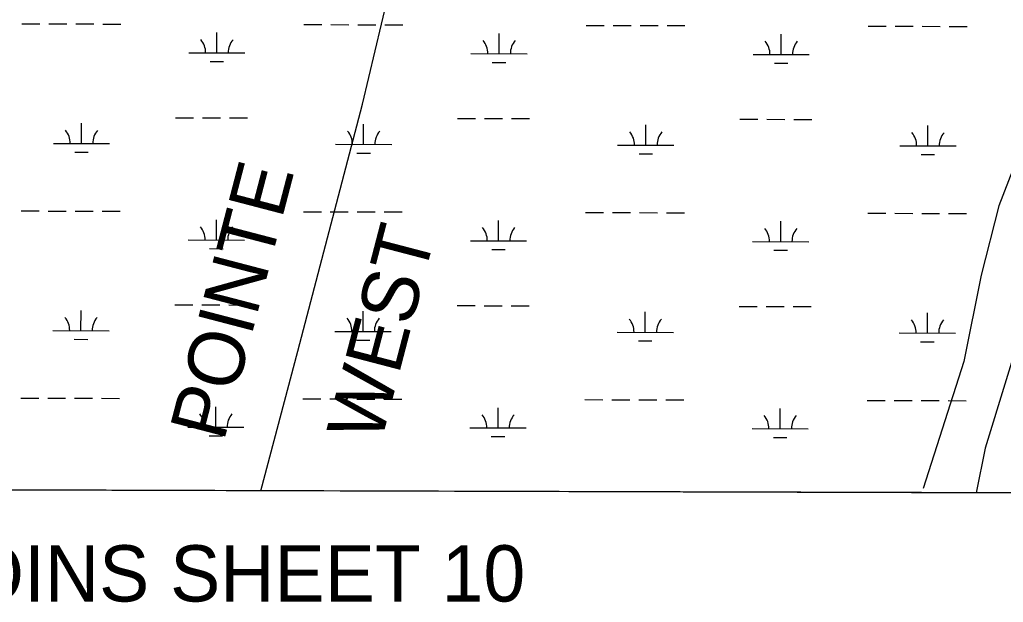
# Model space of a CAD drawing. Extents: x 3161615 to 3199515, y 867541 to 892976.
# Drawn here: x 3178180 to 3179930, y 872774 to 873810 of the extents above; entities that cross this region are included whole.
import ezdxf

# ---------------------------------------------------------------- set-up
doc = ezdxf.new("R2010")
doc.units = 0
for name, color, linetype in [('V-ANNO-TEXT', 7, 'Continuous'), ('V-GRID-FRAM', 7, 'Continuous'), ('V-SITE-VEGE', 7, 'Continuous'), ('V-TOPO-BNDY', 7, 'Continuous'), ('V-TOPO-GNAM-IDEN', 7, 'Continuous'), ('V-TOPO-SHOR', 7, 'Continuous'), ('V-WETL-SWMP', 7, 'Continuous')]:
    doc.layers.add(name, color=color, linetype=linetype)

msp = doc.modelspace()

# ---------------------------------------------------------------- linework, layer by layer
at = {"layer": 'V-GRID-FRAM'}
msp.add_lwpolyline([(3165877.4, 891195.5), (3197229, 891108.8), (3197186.7, 872920.9), (3165819.2, 873007.6), (3165877.4, 891195.5)], dxfattribs=at)
at = {"layer": 'V-SITE-VEGE'}
msp.add_line((3176872, 872977), (3180065.3, 872968.2), dxfattribs=at)
at = {"layer": 'V-TOPO-BNDY'}
for p, q in [((3178790.2, 873659.1), (3178870.4, 873998.9)), ((3178675.1, 873220.3), (3178790.2, 873659.1)), ((3178609, 872972.2), (3178675.1, 873220.3))]:
    msp.add_line(p, q, dxfattribs=at)
at = {"layer": 'V-TOPO-SHOR'}
msp.add_lwpolyline([(3180468.1, 874349.1), (3180252, 874103.5), (3180118, 873888.4), (3180025.3, 873734.7), (3179973.6, 873611.8), (3179922, 873478.5), (3179890.8, 873355.5), (3179859.6, 873201.7), (3179787.2, 872976.1)], dxfattribs=at)
at = {"layer": 'V-WETL-SWMP'}
for p, q in [((3178183.9, 873802.2), (3178215.9, 873802.1)), ((3178231.9, 873802.1), (3178263.9, 873802)), ((3178279.9, 873802), (3178311.9, 873801.9)), ((3178327.9, 873801.8), (3178359.9, 873801.7)), ((3178685.8, 873800.8), (3178717.8, 873800.8)), ((3178733.8, 873800.7), (3178765.8, 873800.6)), ((3178781.8, 873800.6), (3178813.8, 873800.5)), ((3178829.8, 873800.4), (3178861.8, 873800.4)), ((3179187.7, 873799.5), (3179219.7, 873799.4)), ((3179235.7, 873799.3), (3179267.7, 873799.2)), ((3179283.7, 873799.2), (3179315.7, 873799.1)), ((3179331.7, 873799.1), (3179363.7, 873799)), ((3179689.6, 873798.1), (3179721.6, 873798)), ((3178531, 873750.5), (3178531.1, 873786.5)), ((3179032.9, 873749.1), (3179033, 873785.1)), ((3179534.8, 873747.8), (3179534.9, 873783.8)), ((3179737.6, 873797.9), (3179769.6, 873797.8)), ((3179785.6, 873797.8), (3179817.6, 873797.7)), ((3179833.6, 873797.7), (3179865.6, 873797.6)), ((3178481, 873750.7), (3178581, 873750.4)), ((3178982.9, 873749.3), (3179082.9, 873749)), ((3179484.8, 873747.9), (3179584.8, 873747.6)), ((3178519, 873735.1), (3178543, 873735.1)), ((3179020.9, 873733.7), (3179044.9, 873733.7)), ((3179522.8, 873732.4), (3179546.8, 873732.3)), ((3180107.9, 873735), (3179897.8, 873048)), ((3178290.1, 873589.3), (3178290.2, 873625.3)), ((3178457.3, 873635.3), (3178489.3, 873635.2)), ((3178505.3, 873635.2), (3178537.3, 873635.1)), ((3178553.3, 873635), (3178585.3, 873634.9)), ((3178792, 873587.9), (3178792.1, 873623.9)), ((3178959.2, 873633.9), (3178991.2, 873633.8)), ((3179007.2, 873633.8), (3179039.2, 873633.7)), ((3179055.2, 873633.6), (3179087.2, 873633.6)), ((3179461.1, 873632.5), (3179493.1, 873632.4)), ((3179509.1, 873632.4), (3179541.1, 873632.3)), ((3179557.1, 873632.3), (3179589.1, 873632.2)), ((3179293.9, 873586.6), (3179294, 873622.6)), ((3179795.8, 873585.2), (3179795.9, 873621.2)), ((3178240.1, 873589.5), (3178340.1, 873589.2)), ((3178742, 873588.1), (3178842, 873587.8)), ((3178278.1, 873573.9), (3178302.1, 873573.9)), ((3178780, 873572.5), (3178804, 873572.5)), ((3179243.9, 873586.7), (3179343.9, 873586.4)), ((3179281.9, 873571.2), (3179305.9, 873571.1)), ((3179745.8, 873585.3), (3179845.8, 873585)), ((3179783.8, 873569.8), (3179807.8, 873569.7)), ((3178182.9, 873469.6), (3178214.9, 873469.5)), ((3178230.9, 873469.4), (3178262.9, 873469.3)), ((3178278.9, 873469.3), (3178310.9, 873469.2)), ((3178326.9, 873469.2), (3178358.9, 873469.1)), ((3178684.8, 873468.2), (3178716.8, 873468.1)), ((3178732.8, 873468), (3178764.8, 873467.9)), ((3178780.8, 873467.9), (3178812.8, 873467.8)), ((3178828.8, 873467.8), (3178860.8, 873467.7)), ((3179186.7, 873466.8), (3179218.7, 873466.7)), ((3179234.7, 873466.6), (3179266.7, 873466.6)), ((3179282.7, 873466.5), (3179314.7, 873466.4)), ((3179330.7, 873466.4), (3179362.7, 873466.3)), ((3178530.1, 873417.9), (3178530.2, 873453.9)), ((3179032, 873416.5), (3179032.1, 873452.5)), ((3179533.9, 873415.1), (3179534, 873451.1)), ((3179688.7, 873465.4), (3179720.7, 873465.3)), ((3179736.7, 873465.3), (3179768.7, 873465.2)), ((3179784.7, 873465.1), (3179816.7, 873465)), ((3179832.7, 873465), (3179864.7, 873464.9)), ((3178480.1, 873418), (3178580.1, 873417.7)), ((3178982, 873416.6), (3179082, 873416.3)), ((3179483.9, 873415.2), (3179583.9, 873414.9)), ((3178518.1, 873402.5), (3178542.1, 873402.4)), ((3179020, 873401.1), (3179044, 873401)), ((3179521.9, 873399.7), (3179545.9, 873399.6)), ((3178289.2, 873256.7), (3178289.3, 873292.7)), ((3178456.4, 873302.6), (3178488.4, 873302.5)), ((3178504.4, 873302.5), (3178536.4, 873302.4)), ((3178552.4, 873302.4), (3178584.4, 873302.3)), ((3178791.1, 873255.3), (3178791.2, 873291.3)), ((3178958.3, 873301.2), (3178990.3, 873301.2)), ((3179006.3, 873301.1), (3179038.3, 873301)), ((3179054.3, 873301), (3179086.3, 873300.9)), ((3179460.2, 873299.9), (3179492.2, 873299.8)), ((3179508.2, 873299.7), (3179540.2, 873299.6)), ((3179556.2, 873299.6), (3179588.2, 873299.5)), ((3179293, 873253.9), (3179293.1, 873289.9)), ((3179794.9, 873252.5), (3179795, 873288.5)), ((3178239.2, 873256.8), (3178339.2, 873256.5)), ((3178277.2, 873241.3), (3178301.2, 873241.2)), ((3178741.1, 873255.4), (3178841.1, 873255.1)), ((3178779.1, 873239.9), (3178803.1, 873239.8)), ((3179243, 873254), (3179343, 873253.7)), ((3179281, 873238.5), (3179305, 873238.4)), ((3179744.9, 873252.6), (3179844.9, 873252.4)), ((3179782.9, 873237.1), (3179806.9, 873237)), ((3178182, 873136.9), (3178214, 873136.8)), ((3178230, 873136.7), (3178262, 873136.7)), ((3178278, 873136.6), (3178310, 873136.5)), ((3178326, 873136.5), (3178358, 873136.4)), ((3178683.9, 873135.5), (3178715.9, 873135.4)), ((3178731.9, 873135.4), (3178763.9, 873135.3)), ((3178779.9, 873135.2), (3178811.9, 873135.1)), ((3178827.9, 873135.1), (3178859.9, 873135)), ((3179185.8, 873134.1), (3179217.8, 873134)), ((3179233.8, 873134), (3179265.8, 873133.9)), ((3179281.8, 873133.8), (3179313.8, 873133.8)), ((3179329.8, 873133.7), (3179361.8, 873133.6)), ((3178529.2, 873085.2), (3178529.3, 873121.2)), ((3179031.1, 873083.8), (3179031.2, 873119.8)), ((3179533, 873082.4), (3179533.1, 873118.4)), ((3179687.7, 873132.7), (3179719.7, 873132.6)), ((3179735.7, 873132.6), (3179767.7, 873132.5)), ((3179783.7, 873132.5), (3179815.7, 873132.4)), ((3179831.7, 873132.3), (3179863.7, 873132.2)), ((3178479.2, 873085.3), (3178579.2, 873085)), ((3178981.1, 873083.9), (3179081.1, 873083.7)), ((3179483, 873082.5), (3179583, 873082.3)), ((3178517.1, 873069.8), (3178541.1, 873069.7)), ((3179019.1, 873068.4), (3179043.1, 873068.3)), ((3179521, 873067), (3179545, 873066.9)), ((3179897.8, 873048), (3179881.4, 872968.7)), ((3179881.4, 872968.7), (3176862.9, 872977))]:
    msp.add_line(p, q, dxfattribs=at)
for centre, start, end in [((3178475.8, 873751.2), 359.0699, 40.6135), ((3178586.3, 873750.9), 139.0699, 180.6135), ((3178977.7, 873749.8), 359.0699, 40.6135), ((3179088.2, 873749.5), 139.0699, 180.6135), ((3179479.6, 873748.4), 359.0699, 40.6135), ((3179590.1, 873748.1), 139.0699, 180.6135), ((3178234.9, 873590), 359.0699, 40.6135), ((3178345.4, 873589.7), 139.0699, 180.6135), ((3178736.8, 873588.6), 359.0699, 40.6135), ((3178847.3, 873588.3), 139.0699, 180.6135), ((3179238.7, 873587.2), 359.0699, 40.6135), ((3179349.2, 873586.9), 139.0699, 180.6135), ((3179740.6, 873585.8), 359.0699, 40.6135), ((3179851.1, 873585.5), 139.0699, 180.6135), ((3178474.9, 873418.5), 359.0699, 40.6135), ((3178585.4, 873418.2), 139.0699, 180.6135), ((3178976.8, 873417.1), 359.0699, 40.6135), ((3179087.3, 873416.8), 139.0699, 180.6135), ((3179478.7, 873415.7), 359.0699, 40.6135), ((3179589.2, 873415.4), 139.0699, 180.6135), ((3178234, 873257.3), 359.0699, 40.6135), ((3178344.4, 873257), 139.0699, 180.6135), ((3178735.9, 873255.9), 359.0699, 40.6135), ((3178846.3, 873255.6), 139.0699, 180.6135), ((3179237.8, 873254.5), 359.0699, 40.6135), ((3179348.2, 873254.2), 139.0699, 180.6135), ((3179739.7, 873253.1), 359.0699, 40.6135), ((3179850.2, 873252.8), 139.0699, 180.6135), ((3178474, 873085.8), 359.0699, 40.6135), ((3178584.4, 873085.5), 139.0699, 180.6135), ((3178975.9, 873084.4), 359.0699, 40.6135), ((3179086.3, 873084.1), 139.0699, 180.6135), ((3179477.8, 873083), 359.0699, 40.6135), ((3179588.2, 873082.7), 139.0699, 180.6135)]:
    msp.add_arc(centre, 35.2, start, end, dxfattribs=at)

# ---------------------------------------------------------------- texts
at = {"layer": 'V-ANNO-TEXT'}
msp.add_text('JOINS SHEET 10', height=100, dxfattribs=at).set_placement((3178016.9, 872775.2))
at = {"layer": 'V-TOPO-GNAM-IDEN'}
for s, p in [('POINTE', (3178543.2, 873057.9)), ('WEST', (3178822.4, 873054.3))]:
    msp.add_text(s, height=100, rotation=75.3707, dxfattribs=at).set_placement(p)

doc.saveas('drawing.dxf')
